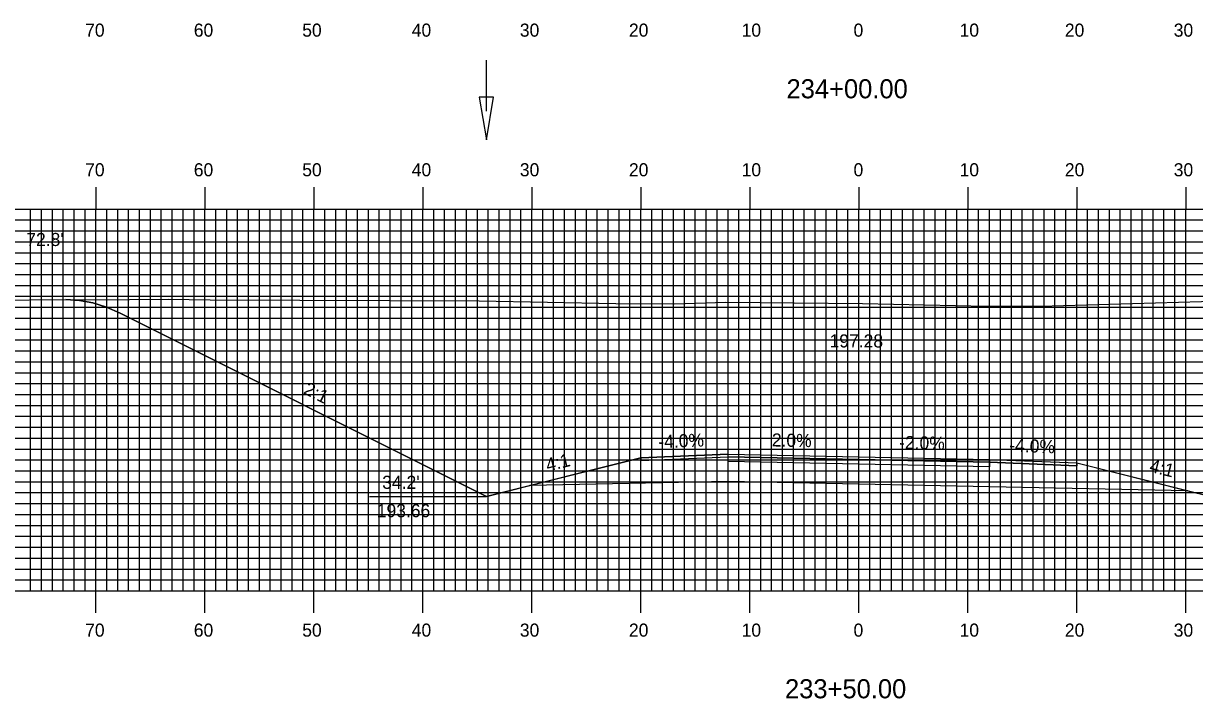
# Model space of a CAD drawing. Extents: x 1799962 to 1800305, y 442591 to 442811.
# Drawn here: x 1800050.9 to 1800158.3, y 442653.8 to 442715.7 of the extents above; entities that cross this region are included whole.
import ezdxf

# ---------------------------------------------------------------- set-up
doc = ezdxf.new("R2010")
doc.units = 0
for name, color, linetype in [('ANNOTATION', 7, 'Continuous'), ('D_Drainage_Ditch_Line', 7, 'Continuous'), ('D_Roadway_Centerline', 7, 'Continuous'), ('D_Roadway_Centerline_Text', 7, 'Continuous'), ('D_Roadway_Edge_Shoulder', 7, 'Continuous'), ('D_Roadway_Edge_TW', 7, 'Continuous'), ('D_Roadway_Pavement', 7, 'Continuous'), ('D_Roadway_SlopeLines', 7, 'Continuous'), ('D_Roadway_SubGrade', 7, 'Continuous'), ('D_Text_Standard', 7, 'Continuous'), ('H_V ANNOTATION', 7, 'Continuous'), ('MAJOR', 7, 'Continuous'), ('MINOR', 7, 'Continuous'), ('PDRAIN', 7, 'Continuous'), ('S_Roadway_Centerline', 7, 'Continuous')]:
    doc.layers.add(name, color=color, linetype=linetype)

msp = doc.modelspace()

# ---------------------------------------------------------------- linework, layer by layer
at = {"layer": 'D_Drainage_Ditch_Line'}
msp.add_line((1800093.35, 442707.63), (1800093.35, 442712.33), dxfattribs=at)
msp.add_lwpolyline([(1800094.01, 442708.94), (1800092.69, 442708.94), (1800093.35, 442705)], close=True, dxfattribs=at)
at = {"layer": 'D_Roadway_Centerline'}
msp.add_lwpolyline([(1800054.75, 442690.37), (1800056, 442690.29), (1800057.25, 442690.06), (1800058.5, 442689.67), (1800059.75, 442689.13), (1800093.35, 442672.33), (1800097.35, 442673.33), (1800107.52, 442675.87), (1800115.52, 442676.19), (1800127.52, 442675.95), (1800139.52, 442675.71), (1800147.52, 442675.39), (1800157.7, 442672.85), (1800161.7, 442671.85), (1800194.25, 442688.12), (1800195.5, 442688.67), (1800196.75, 442689.05), (1800198, 442689.26), (1800199.25, 442689.32)], dxfattribs=at)
at = {"layer": 'D_Roadway_Edge_Shoulder'}
for points in [[(1800115.52, 442676.19), (1800107.52, 442675.87), (1800107.52, 442675.62), (1800115.52, 442675.94)], [(1800139.52, 442675.71), (1800147.52, 442675.39), (1800147.52, 442675.14), (1800139.52, 442675.46)]]:
    msp.add_lwpolyline(points, close=True, dxfattribs=at)
at = {"layer": 'D_Roadway_Edge_TW'}
msp.add_lwpolyline([(1800115.52, 442675.94), (1800115.52, 442676.19), (1800127.52, 442675.95), (1800139.52, 442675.71), (1800139.52, 442675.46), (1800127.52, 442675.7)], close=True, dxfattribs=at)
at = {"layer": 'D_Roadway_Pavement'}
msp.add_lwpolyline([(1800115.52, 442675.52), (1800115.52, 442675.94), (1800127.52, 442675.7), (1800139.52, 442675.46), (1800139.52, 442675.04), (1800127.52, 442675.28)], close=True, dxfattribs=at)
at = {"layer": 'D_Roadway_SlopeLines'}
for points in [[(1800093.35, 442672.33), (1800059.75, 442689.13), (1800058.5, 442689.67), (1800057.25, 442690.06), (1800056, 442690.29), (1800054.75, 442690.37)], [(1800107.52, 442675.87), (1800093.35, 442672.33)], [(1800147.52, 442675.39), (1800161.7, 442671.85)]]:
    msp.add_lwpolyline(points, dxfattribs=at)
at = {"layer": 'D_Roadway_SubGrade'}
msp.add_lwpolyline([(1800115.52, 442673.69), (1800097.35, 442673.33), (1800107.52, 442675.87), (1800107.52, 442675.62), (1800115.52, 442675.94), (1800127.52, 442675.7), (1800139.52, 442675.46), (1800147.52, 442675.14), (1800147.52, 442675.39), (1800157.7, 442672.85), (1800139.52, 442673.21), (1800127.52, 442673.45)], close=True, dxfattribs=at)
at = {"layer": 'MAJOR'}
for p, q in [((1800057.52, 442700.67), (1800057.52, 442698.67)), ((1800067.52, 442700.67), (1800067.52, 442698.67)), ((1800077.52, 442700.67), (1800077.52, 442698.67)), ((1800087.52, 442700.67), (1800087.52, 442698.67)), ((1800097.52, 442700.67), (1800097.52, 442698.67)), ((1800107.52, 442700.67), (1800107.52, 442698.67)), ((1800117.52, 442700.67), (1800117.52, 442698.67)), ((1800127.52, 442700.67), (1800127.52, 442698.67)), ((1800137.52, 442700.67), (1800137.52, 442698.67)), ((1800147.52, 442700.67), (1800147.52, 442698.67)), ((1800157.52, 442700.67), (1800157.52, 442698.67)), ((1799987.52, 442698.67), (1800267.52, 442698.67)), ((1799987.52, 442698.67), (1800267.52, 442698.67)), ((1800057.52, 442663.67), (1800057.52, 442698.67)), ((1800067.52, 442663.67), (1800067.52, 442698.67)), ((1800077.52, 442663.67), (1800077.52, 442698.67)), ((1800087.52, 442663.67), (1800087.52, 442698.67)), ((1800097.52, 442663.67), (1800097.52, 442698.67)), ((1800107.52, 442663.67), (1800107.52, 442698.67)), ((1800117.52, 442663.67), (1800117.52, 442698.67)), ((1800127.52, 442663.67), (1800127.52, 442698.67)), ((1800137.52, 442663.67), (1800137.52, 442698.67)), ((1800147.52, 442663.67), (1800147.52, 442698.67)), ((1800157.52, 442663.67), (1800157.52, 442698.67)), ((1799987.52, 442693.67), (1800267.52, 442693.67)), ((1799987.52, 442688.67), (1800267.52, 442688.67)), ((1799987.52, 442683.67), (1800267.52, 442683.67)), ((1799987.52, 442678.67), (1800267.52, 442678.67)), ((1799987.52, 442673.67), (1800267.52, 442673.67)), ((1799987.52, 442668.67), (1800267.52, 442668.67)), ((1799987.52, 442663.67), (1800267.52, 442663.67)), ((1799987.52, 442663.67), (1800267.52, 442663.67)), ((1800057.52, 442661.66), (1800057.52, 442663.67)), ((1800067.52, 442661.66), (1800067.52, 442663.67)), ((1800077.52, 442661.66), (1800077.52, 442663.67)), ((1800087.52, 442661.66), (1800087.52, 442663.67)), ((1800097.52, 442661.66), (1800097.52, 442663.67)), ((1800107.52, 442661.66), (1800107.52, 442663.67)), ((1800117.52, 442661.66), (1800117.52, 442663.67)), ((1800127.52, 442661.66), (1800127.52, 442663.67)), ((1800137.52, 442661.66), (1800137.52, 442663.67)), ((1800147.52, 442661.66), (1800147.52, 442663.67)), ((1800157.52, 442661.66), (1800157.52, 442663.67))]:
    msp.add_line(p, q, dxfattribs=at)
at = {"layer": 'MINOR'}
for p, q in [((1800051.52, 442663.67), (1800051.52, 442698.67)), ((1800052.52, 442663.67), (1800052.52, 442698.67)), ((1800053.52, 442663.67), (1800053.52, 442698.67)), ((1800054.52, 442663.67), (1800054.52, 442698.67)), ((1800055.52, 442663.67), (1800055.52, 442698.67)), ((1800056.52, 442663.67), (1800056.52, 442698.67)), ((1800058.52, 442663.67), (1800058.52, 442698.67)), ((1800059.52, 442663.67), (1800059.52, 442698.67)), ((1800060.52, 442663.67), (1800060.52, 442698.67)), ((1800061.52, 442663.67), (1800061.52, 442698.67)), ((1800062.52, 442663.67), (1800062.52, 442698.67)), ((1800063.52, 442663.67), (1800063.52, 442698.67)), ((1800064.52, 442663.67), (1800064.52, 442698.67)), ((1800065.52, 442663.67), (1800065.52, 442698.67)), ((1800066.52, 442663.67), (1800066.52, 442698.67)), ((1800068.52, 442663.67), (1800068.52, 442698.67)), ((1800069.52, 442663.67), (1800069.52, 442698.67)), ((1800070.52, 442663.67), (1800070.52, 442698.67)), ((1800071.52, 442663.67), (1800071.52, 442698.67)), ((1800072.52, 442663.67), (1800072.52, 442698.67)), ((1800073.52, 442663.67), (1800073.52, 442698.67)), ((1800074.52, 442663.67), (1800074.52, 442698.67)), ((1800075.52, 442663.67), (1800075.52, 442698.67)), ((1800076.52, 442663.67), (1800076.52, 442698.67)), ((1800078.52, 442663.67), (1800078.52, 442698.67)), ((1800079.52, 442663.67), (1800079.52, 442698.67)), ((1800080.52, 442663.67), (1800080.52, 442698.67)), ((1800081.52, 442663.67), (1800081.52, 442698.67)), ((1800082.52, 442663.67), (1800082.52, 442698.67)), ((1800083.52, 442663.67), (1800083.52, 442698.67)), ((1800084.52, 442663.67), (1800084.52, 442698.67)), ((1800085.52, 442663.67), (1800085.52, 442698.67)), ((1800086.52, 442663.67), (1800086.52, 442698.67)), ((1800088.52, 442663.67), (1800088.52, 442698.67)), ((1800089.52, 442663.67), (1800089.52, 442698.67)), ((1800090.52, 442663.67), (1800090.52, 442698.67)), ((1800091.52, 442663.67), (1800091.52, 442698.67)), ((1800092.52, 442663.67), (1800092.52, 442698.67)), ((1800093.52, 442663.67), (1800093.52, 442698.67)), ((1800094.52, 442663.67), (1800094.52, 442698.67)), ((1800095.52, 442663.67), (1800095.52, 442698.67)), ((1800096.52, 442663.67), (1800096.52, 442698.67)), ((1800098.52, 442663.67), (1800098.52, 442698.67)), ((1800099.52, 442663.67), (1800099.52, 442698.67)), ((1800100.52, 442663.67), (1800100.52, 442698.67)), ((1800101.52, 442663.67), (1800101.52, 442698.67)), ((1800102.52, 442663.67), (1800102.52, 442698.67)), ((1800103.52, 442663.67), (1800103.52, 442698.67)), ((1800104.52, 442663.67), (1800104.52, 442698.67)), ((1800105.52, 442663.67), (1800105.52, 442698.67)), ((1800106.52, 442663.67), (1800106.52, 442698.67)), ((1800108.52, 442663.67), (1800108.52, 442698.67)), ((1800109.52, 442663.67), (1800109.52, 442698.67)), ((1800110.52, 442663.67), (1800110.52, 442698.67)), ((1800111.52, 442663.67), (1800111.52, 442698.67)), ((1800112.52, 442663.67), (1800112.52, 442698.67)), ((1800113.52, 442663.67), (1800113.52, 442698.67)), ((1800114.52, 442663.67), (1800114.52, 442698.67)), ((1800115.52, 442663.67), (1800115.52, 442698.67)), ((1800116.52, 442663.67), (1800116.52, 442698.67)), ((1800118.52, 442663.67), (1800118.52, 442698.67)), ((1800119.52, 442663.67), (1800119.52, 442698.67)), ((1800120.52, 442663.67), (1800120.52, 442698.67)), ((1800121.52, 442663.67), (1800121.52, 442698.67)), ((1800122.52, 442663.67), (1800122.52, 442698.67)), ((1800123.52, 442663.67), (1800123.52, 442698.67)), ((1800124.52, 442663.67), (1800124.52, 442698.67)), ((1800125.52, 442663.67), (1800125.52, 442698.67)), ((1800126.52, 442663.67), (1800126.52, 442698.67)), ((1800128.52, 442663.67), (1800128.52, 442698.67)), ((1800129.52, 442663.67), (1800129.52, 442698.67)), ((1800130.52, 442663.67), (1800130.52, 442698.67)), ((1800131.52, 442663.67), (1800131.52, 442698.67)), ((1800132.52, 442663.67), (1800132.52, 442698.67)), ((1800133.52, 442663.67), (1800133.52, 442698.67)), ((1800134.52, 442663.67), (1800134.52, 442698.67)), ((1800135.52, 442663.67), (1800135.52, 442698.67)), ((1800136.52, 442663.67), (1800136.52, 442698.67)), ((1800138.52, 442663.67), (1800138.52, 442698.67)), ((1800139.52, 442663.67), (1800139.52, 442698.67)), ((1800140.52, 442663.67), (1800140.52, 442698.67)), ((1800141.52, 442663.67), (1800141.52, 442698.67)), ((1800142.52, 442663.67), (1800142.52, 442698.67)), ((1800143.52, 442663.67), (1800143.52, 442698.67)), ((1800144.52, 442663.67), (1800144.52, 442698.67)), ((1800145.52, 442663.67), (1800145.52, 442698.67)), ((1800146.52, 442663.67), (1800146.52, 442698.67)), ((1800148.52, 442663.67), (1800148.52, 442698.67)), ((1800149.52, 442663.67), (1800149.52, 442698.67)), ((1800150.52, 442663.67), (1800150.52, 442698.67)), ((1800151.52, 442663.67), (1800151.52, 442698.67)), ((1800152.52, 442663.67), (1800152.52, 442698.67)), ((1800153.52, 442663.67), (1800153.52, 442698.67)), ((1800154.52, 442663.67), (1800154.52, 442698.67)), ((1800155.52, 442663.67), (1800155.52, 442698.67)), ((1800156.52, 442663.67), (1800156.52, 442698.67)), ((1799987.52, 442697.67), (1800267.52, 442697.67)), ((1799987.52, 442696.67), (1800267.52, 442696.67)), ((1799987.52, 442695.67), (1800267.52, 442695.67)), ((1799987.52, 442694.67), (1800267.52, 442694.67)), ((1799987.52, 442692.67), (1800267.52, 442692.67)), ((1799987.52, 442691.67), (1800267.52, 442691.67)), ((1799987.52, 442690.67), (1800267.52, 442690.67)), ((1799987.52, 442689.67), (1800267.52, 442689.67)), ((1799987.52, 442687.67), (1800267.52, 442687.67)), ((1799987.52, 442686.67), (1800267.52, 442686.67)), ((1799987.52, 442685.67), (1800267.52, 442685.67)), ((1799987.52, 442684.67), (1800267.52, 442684.67)), ((1799987.52, 442682.67), (1800267.52, 442682.67)), ((1799987.52, 442681.67), (1800267.52, 442681.67)), ((1799987.52, 442680.67), (1800267.52, 442680.67)), ((1799987.52, 442679.67), (1800267.52, 442679.67)), ((1799987.52, 442677.67), (1800267.52, 442677.67)), ((1799987.52, 442676.67), (1800267.52, 442676.67)), ((1799987.52, 442675.67), (1800267.52, 442675.67)), ((1799987.52, 442674.67), (1800267.52, 442674.67)), ((1799987.52, 442672.67), (1800267.52, 442672.67)), ((1799987.52, 442671.67), (1800267.52, 442671.67)), ((1799987.52, 442670.67), (1800267.52, 442670.67)), ((1799987.52, 442669.67), (1800267.52, 442669.67)), ((1799987.52, 442667.67), (1800267.52, 442667.67)), ((1799987.52, 442666.67), (1800267.52, 442666.67)), ((1799987.52, 442665.67), (1800267.52, 442665.67)), ((1799987.52, 442664.67), (1800267.52, 442664.67))]:
    msp.add_line(p, q, dxfattribs=at)
at = {"layer": 'PDRAIN'}
msp.add_line((1800082.63, 442672.33), (1800093.35, 442672.33), dxfattribs=at)
at = {"layer": 'S_Roadway_Centerline'}
msp.add_lwpolyline([(1799987.52, 442689.6), (1799993.61, 442689.62), (1800013.84, 442690.07), (1800017.14, 442690.1), (1800018.53, 442690.21), (1800036.88, 442690.37), (1800042.19, 442690.31), (1800060.6, 442690.39), (1800064.16, 442690.4), (1800068.01, 442690.34), (1800092.68, 442690.26), (1800105.22, 442690.02), (1800110.64, 442689.98), (1800115.31, 442690.13), (1800127.86, 442690.02), (1800139.25, 442689.77), (1800144.2, 442689.77), (1800163.19, 442690.31)], dxfattribs=at)

# ---------------------------------------------------------------- texts
at = {"layer": 'ANNOTATION'}
for s, rotation, p in [('2:1', 333.4349, (1800076.48, 442681.79)), ('-4.0%', 2.2906, (1800109.15, 442676.74)), ('2.0%', 358.8542, (1800119.53, 442676.91)), ('-2.0%', 358.8542, (1800131.21, 442676.68)), ('-4.0%', 357.7094, (1800141.31, 442676.44)), ('4:1', 14.0362, (1800098.97, 442674.59)), ('4:1', 345.9638, (1800154.12, 442674.6))]:
    msp.add_text(s, height=1.2, rotation=rotation, dxfattribs=at).set_placement(p)
for s, p in [("34.2'", (1800083.79, 442673.02)), ('193.66', (1800083.29, 442670.42))]:
    msp.add_text(s, height=1.2, dxfattribs=at).set_placement(p)
at = {"layer": 'D_Roadway_Centerline'}
for s, p in [('C', (1800127.52, 442675.95)), ('L', (1800127.52, 442675.94))]:
    msp.add_text(s, height=0.0146, dxfattribs=at).set_placement(p)
at = {"layer": 'D_Roadway_Centerline_Text'}
msp.add_text('197.28', height=1.2, dxfattribs=at).set_placement((1800124.84, 442685.98))
at = {"layer": 'D_Text_Standard'}
msp.add_text("72.8'", height=1.2, dxfattribs=at).set_placement((1800051.13, 442695.28))
at = {"layer": 'H_V ANNOTATION'}
for s, height, p in [('70', 1.2, (1800056.53, 442714.47)), ('60', 1.2, (1800066.5, 442714.47)), ('50', 1.2, (1800076.45, 442714.47)), ('40', 1.2, (1800086.5, 442714.47)), ('30', 1.2, (1800096.42, 442714.47)), ('20', 1.2, (1800106.43, 442714.47)), ('10', 1.2, (1800116.77, 442714.47)), ('0', 1.2, (1800127.04, 442714.47)), ('10', 1.2, (1800136.77, 442714.47)), ('20', 1.2, (1800146.43, 442714.47)), ('30', 1.2, (1800156.42, 442714.47)), ('234+00.00', 1.75, (1800120.89, 442708.82)), ('70', 1.2, (1800056.53, 442701.67)), ('60', 1.2, (1800066.5, 442701.67)), ('50', 1.2, (1800076.45, 442701.67)), ('40', 1.2, (1800086.5, 442701.67)), ('30', 1.2, (1800096.42, 442701.67)), ('20', 1.2, (1800106.43, 442701.67)), ('10', 1.2, (1800116.77, 442701.67)), ('0', 1.2, (1800127.04, 442701.67)), ('10', 1.2, (1800136.77, 442701.67)), ('20', 1.2, (1800146.43, 442701.67)), ('30', 1.2, (1800156.42, 442701.67)), ('70', 1.2, (1800056.53, 442659.47)), ('60', 1.2, (1800066.5, 442659.47)), ('50', 1.2, (1800076.45, 442659.47)), ('40', 1.2, (1800086.5, 442659.47)), ('30', 1.2, (1800096.42, 442659.47)), ('20', 1.2, (1800106.43, 442659.47)), ('10', 1.2, (1800116.77, 442659.47)), ('0', 1.2, (1800127.04, 442659.47)), ('10', 1.2, (1800136.77, 442659.47)), ('20', 1.2, (1800146.43, 442659.47)), ('30', 1.2, (1800156.42, 442659.47)), ('233+50.00', 1.75, (1800120.75, 442653.82))]:
    msp.add_text(s, height=height, dxfattribs=at).set_placement(p)

doc.saveas('drawing.dxf')
